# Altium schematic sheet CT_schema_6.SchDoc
size 388 x 258 mm
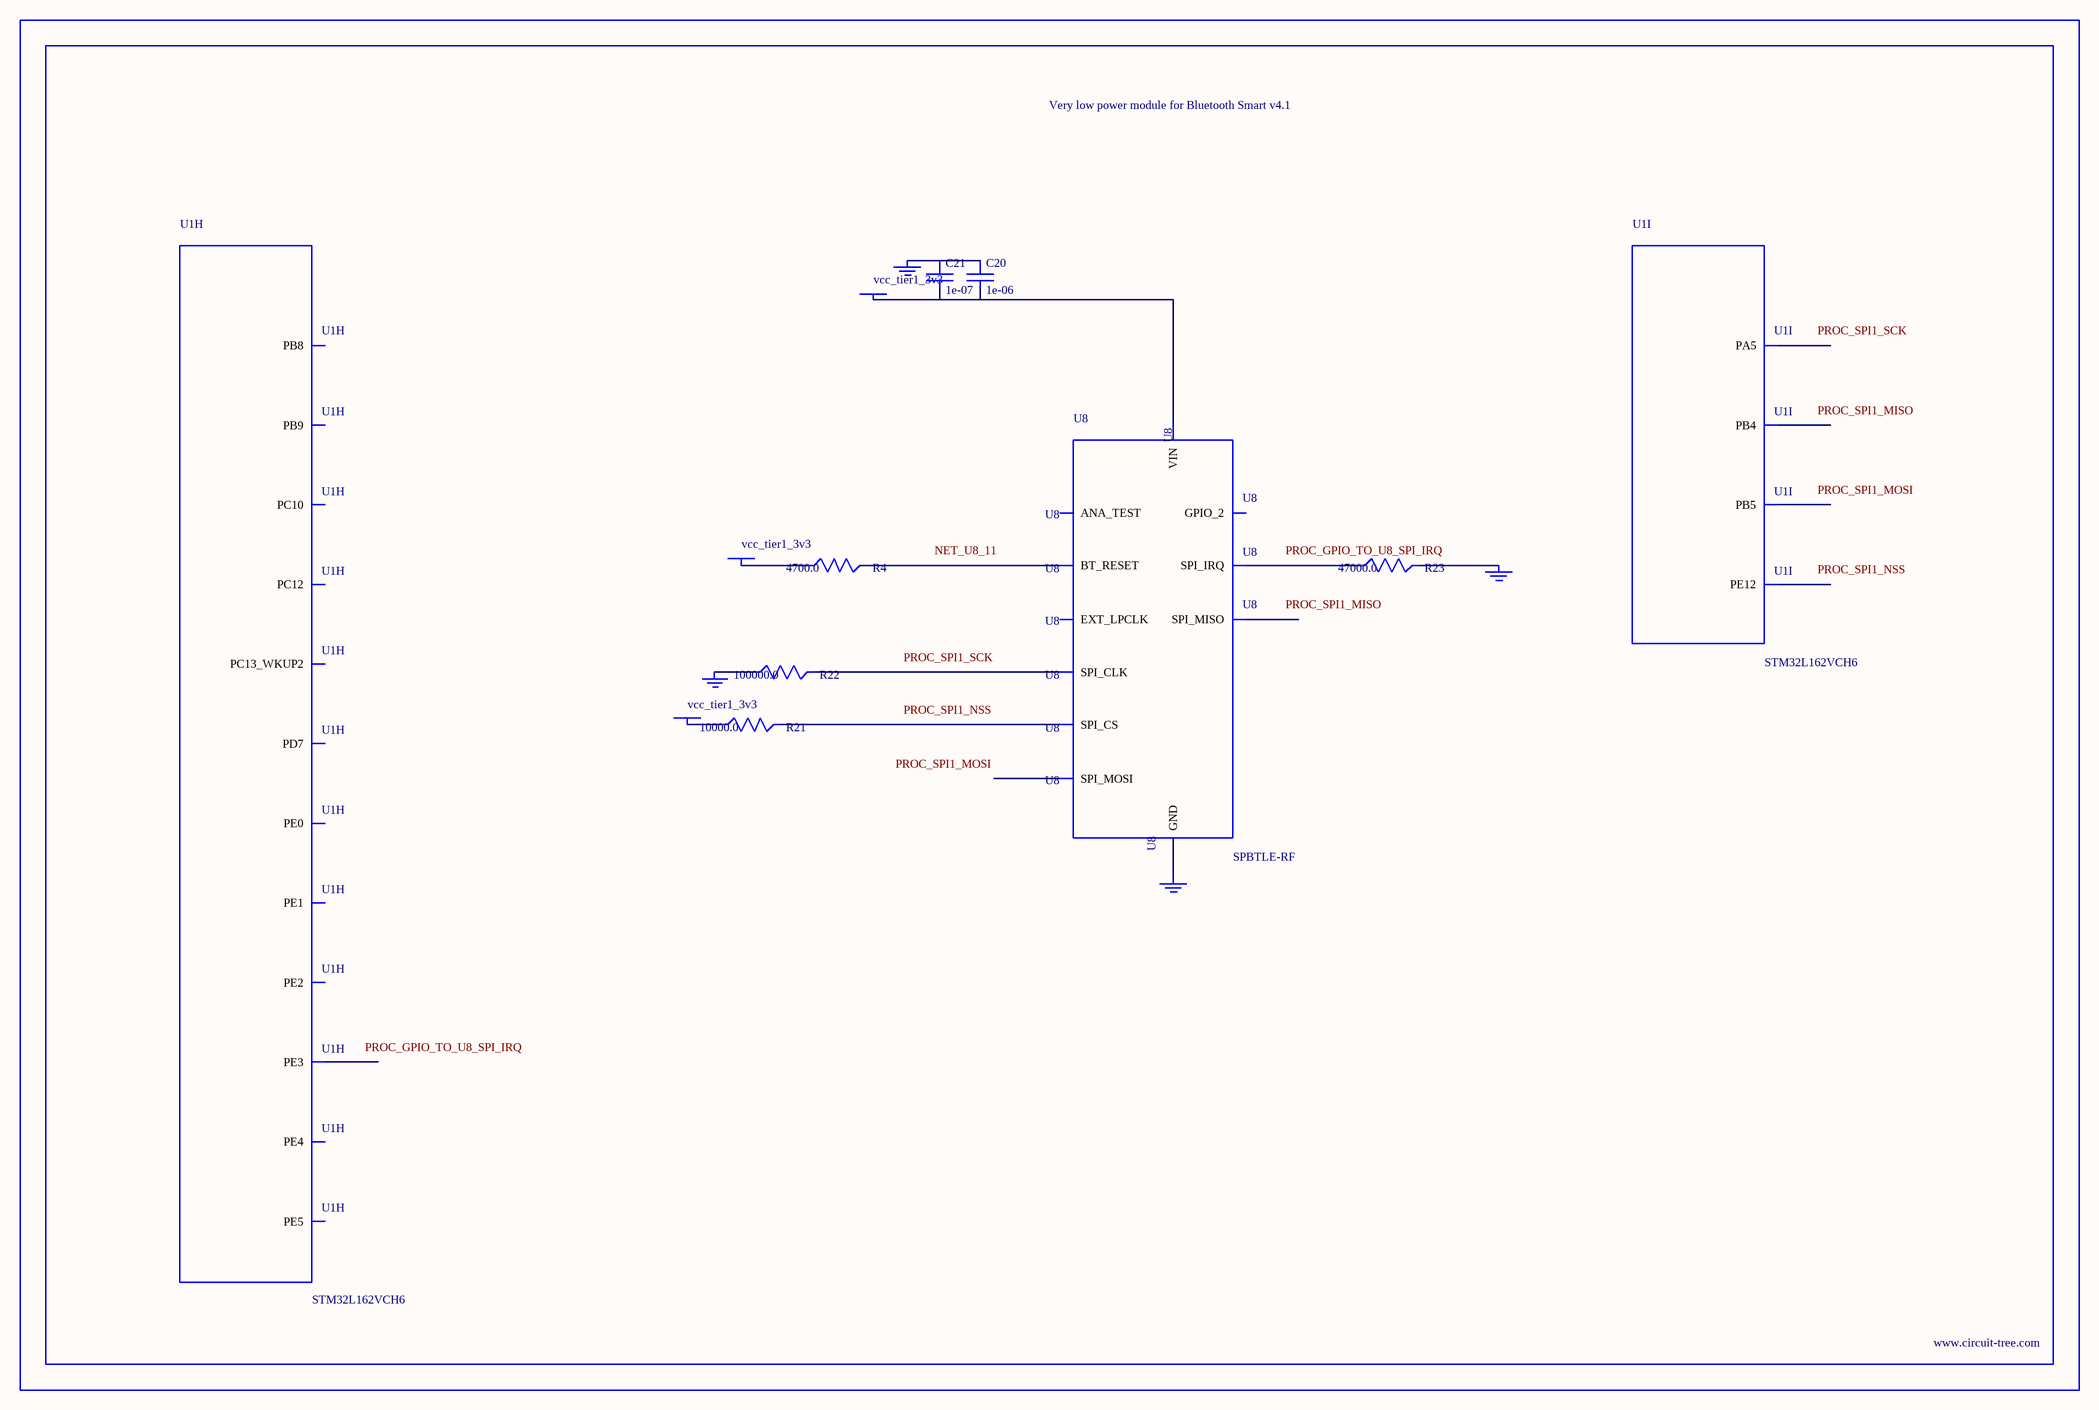
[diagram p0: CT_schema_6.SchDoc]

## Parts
BORDER5  (no value)
C20  1e-06  [C0603]
C21  1e-07  [C0402]
GND_INSTANCE_5_0  (no value)
GND_INSTANCE_5_1  (no value)
GND_INSTANCE_5_2  (no value)
GND_INSTANCE_5_3  (no value)
POWER_INSTANCE_5_0  vcc_tier1_3v3
POWER_INSTANCE_5_1  vcc_tier1_3v3
POWER_INSTANCE_5_2  vcc_tier1_3v3
R4  4700.0  [R0603]
R21  10000.0  [R0603]
R22  100000.0  [R0603]
R23  47000.0  [R0603]
U1  STM32L162VCH6  [UFBGA100]  (parts H,I of 9)
U8  SPBTLE-RF  [XCVR_SPBTLE-RF]

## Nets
NetC20_1: C20.1 C21.1 GND_INSTANCE_5_1.0(GND)
NetC20_2: C20.2 C21.2 POWER_INSTANCE_5_0.0(PWR) U8.5(VIN)
NetGND_INSTANCE_5_0_0: GND_INSTANCE_5_0.0(GND) R23.2
NetGND_INSTANCE_5_2_0: GND_INSTANCE_5_2.0(GND) R22.1
NetGND_INSTANCE_5_3_0: GND_INSTANCE_5_3.0(GND) U8.6(GND)
NetPOWER_INSTANCE_5_1_0: POWER_INSTANCE_5_1.0(PWR) R21.1
NetPOWER_INSTANCE_5_2_0: POWER_INSTANCE_5_2.0(PWR) R4.1
NetR4_2: R4.2 U8.11(BT_RESET)
NetR21_2: R21.2 U8.10(SPI_CS)
NetR22_2: R22.2 U8.7(SPI_CLK)
NetR23_1: R23.1 U8.4(SPI_IRQ)

Not connected (* = marked no-connect by the designer): U1 A1(PE3) A2(PE1) A3(PB8) A5(PD7) A7(PB4) B1(PE4) B2(PE2) B3(PB9) B10(PC12) B11(PC10) C1(PC13_WKUP2) C2(PE5) C3(PE0) C5(PB5) K4(PA5) L9(PE12); U8 1(EXT_LPCLK) 2(GPIO_2) 3(ANA_TEST) 8(SPI_MISO) 9(SPI_MOSI)

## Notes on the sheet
- Labels drawn without touching a wire or pin: NET_U8_11, PROC_GPIO_TO_U8_SPI_IRQ, PROC_SPI1_MISO, PROC_SPI1_MOSI, PROC_SPI1_NSS, PROC_SPI1_SCK

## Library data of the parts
BORDER5 = BORDER_PAGE5
C20 = C0603C105K3RACTU
C21 = C0402C104K3RACTU
GND_INSTANCE_5_0-GND_INSTANCE_5_3 = GND
POWER_INSTANCE_5_0-POWER_INSTANCE_5_2 = PWR
R4 = RC0603JR-074K7L
R21 = RC0603JR-0710KL
R22 = RC0603JR-07100KL
R23 = RC0603JR-0747KL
